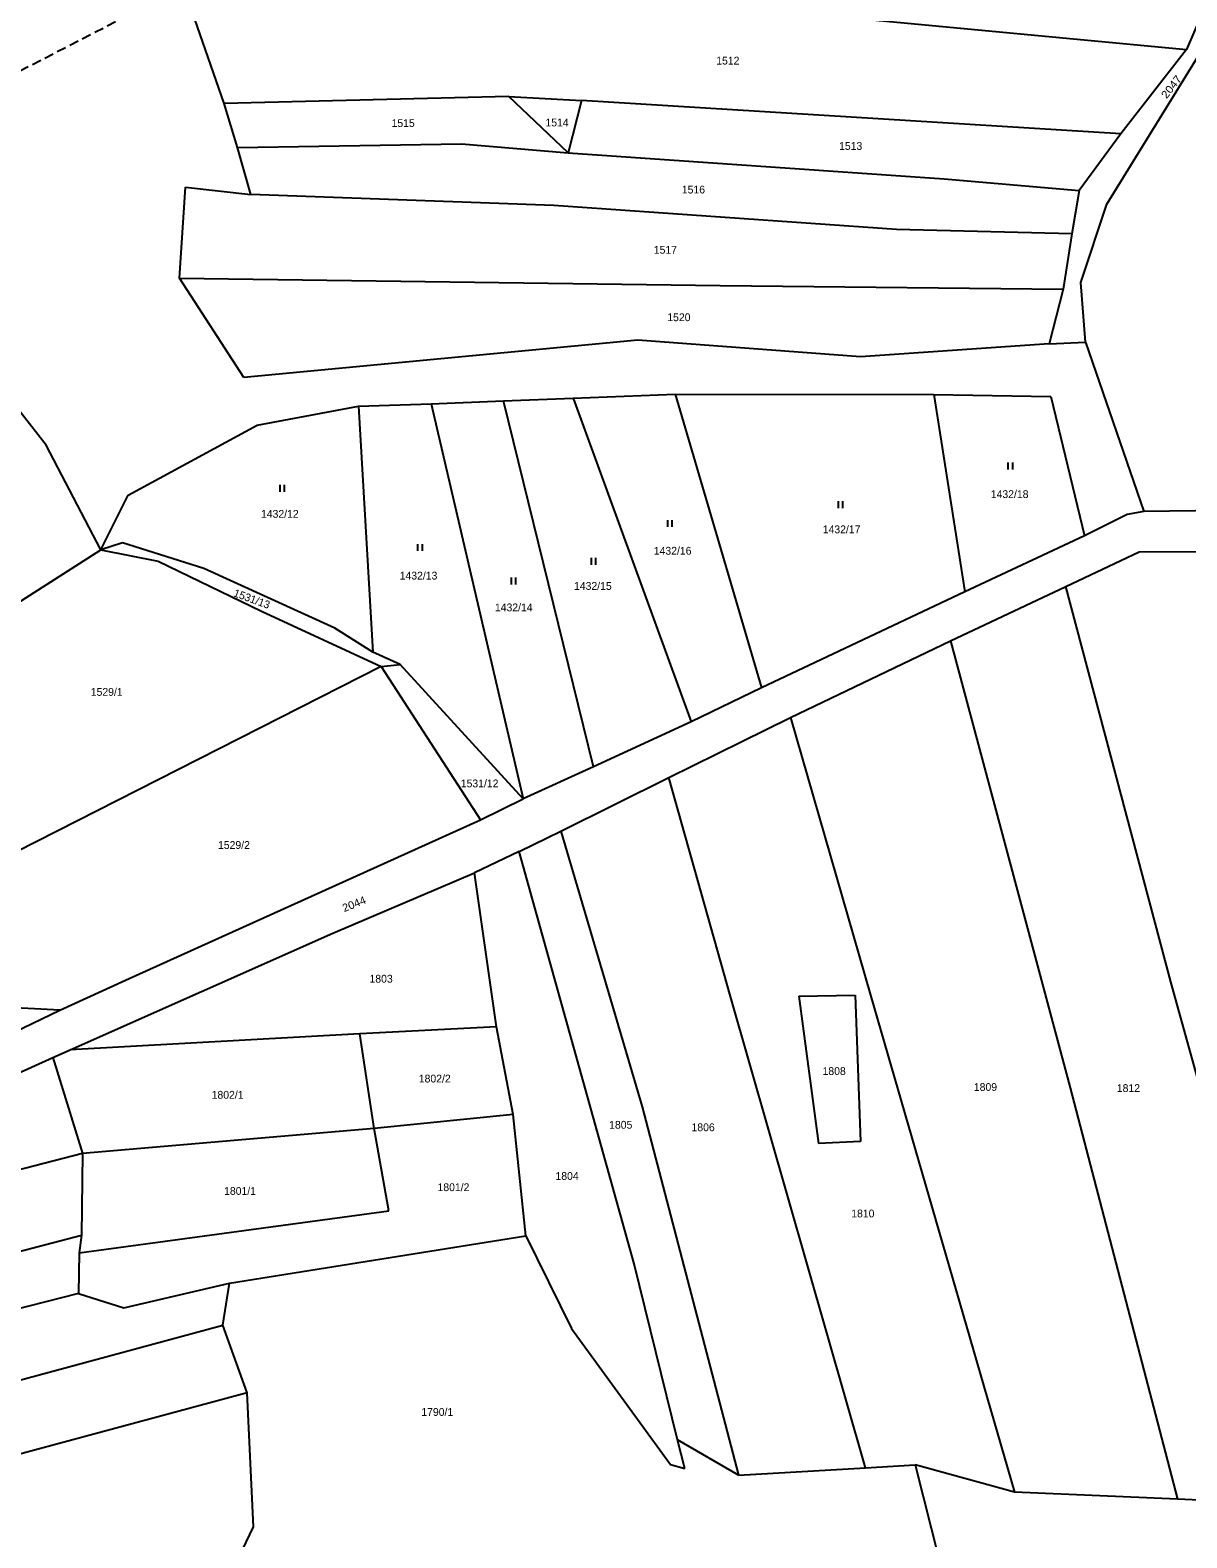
# Model space of a CAD drawing. Extents: x -820420 to -815896, y -1105820 to -1103643.
# Drawn here: x -819110.8 to -818858.6, y -1105141.1 to -1104812.4 of the extents above; entities that cross this region are included whole.
import ezdxf
from ezdxf.enums import TextEntityAlignment as Align

# ---------------------------------------------------------------- set-up
doc = ezdxf.new("R2010")
doc.units = 0
doc.header["$LTSCALE"] = 0.68
doc.linetypes.add('MEDIUM_DASHED', pattern=[4.5, 3, -1.5])
for name, color, linetype, lineweight in [('1', 7, 'Continuous', 25), ('3', 7, 'Continuous', 25), ('6', 7, 'Continuous', 25)]:
    doc.layers.add(name, color=color, linetype=linetype, lineweight=lineweight)
doc.layers.add('2', color=7, linetype='Continuous')

msp = doc.modelspace()

# ---------------------------------------------------------------- linework, layer by layer
at = {"layer": '1'}
for p, q in [((-819068.53, -1104828.41), (-819081.61, -1104790.49)), ((-818852.44, -1104802.17), (-818858.67, -1104816.63)), ((-818985.5, -1104804.65), (-818858.67, -1104816.63)), ((-818876.06, -1104850.4), (-818855.17, -1104816.62)), ((-818858.67, -1104816.63), (-818872.99, -1104835.02)), ((-819006.46, -1104826.94), (-819068.53, -1104828.41)), ((-819065.62, -1104838.05), (-819068.53, -1104828.41)), ((-819006.46, -1104826.94), (-818990.59, -1104827.81)), ((-818993.5, -1104839.21), (-819006.46, -1104826.94)), ((-818990.59, -1104827.81), (-818993.5, -1104839.21)), ((-818872.99, -1104835.02), (-818990.59, -1104827.81)), ((-818872.99, -1104835.02), (-818882.11, -1104847.37)), ((-819065.62, -1104838.05), (-819016.76, -1104837.26)), ((-819062.66, -1104848.28), (-819065.62, -1104838.05)), ((-819016.76, -1104837.26), (-818993.5, -1104839.21)), ((-818993.5, -1104839.21), (-818911.48, -1104844.88)), ((-818911.48, -1104844.88), (-818882.11, -1104847.37)), ((-819078.23, -1104866.53), (-819076.91, -1104846.64)), ((-819076.91, -1104846.64), (-819062.66, -1104848.28)), ((-818996.6, -1104850.68), (-819062.66, -1104848.28)), ((-818882.11, -1104847.37), (-818883.71, -1104856.87)), ((-818921.91, -1104855.87), (-818996.6, -1104850.68)), ((-818881.75, -1104867.43), (-818876.06, -1104850.4)), ((-818883.71, -1104856.87), (-818921.91, -1104855.87)), ((-818883.71, -1104856.87), (-818885.55, -1104868.9)), ((-819078.23, -1104866.53), (-818960.37, -1104868.12)), ((-819064.19, -1104888.18), (-819078.23, -1104866.53)), ((-818960.37, -1104868.12), (-818885.55, -1104868.9)), ((-818885.55, -1104868.9), (-818888.62, -1104880.85)), ((-818880.7, -1104880.5), (-818881.75, -1104867.43)), ((-818978.3, -1104880.01), (-819064.19, -1104888.18)), ((-818929.78, -1104883.69), (-818978.3, -1104880.01)), ((-818888.62, -1104880.85), (-818929.78, -1104883.69)), ((-818888.62, -1104880.85), (-818880.7, -1104880.5)), ((-818880.7, -1104880.5), (-818867.95, -1104917.39)), ((-819107.3, -1104902.93), (-819118.8, -1104888.25)), ((-818992.39, -1104892.68), (-818970.15, -1104891.82)), ((-818970.15, -1104891.82), (-818951.37, -1104955.85)), ((-818970.15, -1104891.82), (-818913.75, -1104891.89)), ((-818913.75, -1104891.89), (-818888.27, -1104892.33)), ((-818913.75, -1104891.89), (-818907.04, -1104934.91)), ((-818888.27, -1104892.33), (-818880.93, -1104922.67)), ((-819061.32, -1104898.56), (-819039.21, -1104894.44)), ((-819039.21, -1104894.44), (-819023.33, -1104893.89)), ((-819039.21, -1104894.44), (-819036.11, -1104948.04)), ((-819023.33, -1104893.89), (-819007.56, -1104893.27)), ((-819023.33, -1104893.89), (-819003.34, -1104980.04)), ((-819007.56, -1104893.27), (-818992.39, -1104892.68)), ((-818987.94, -1104973.07), (-819007.56, -1104893.27)), ((-818992.39, -1104892.68), (-818966.65, -1104963.21)), ((-819089.43, -1104913.83), (-819061.32, -1104898.56)), ((-819095.36, -1104925.76), (-819107.3, -1104902.93)), ((-819095.36, -1104925.76), (-819089.43, -1104913.83)), ((-818871.62, -1104918.02), (-818880.93, -1104922.67)), ((-818867.95, -1104917.39), (-818871.62, -1104918.02)), ((-818821.74, -1104916.82), (-818867.95, -1104917.39)), ((-819090.63, -1104924.18), (-819095.36, -1104925.76)), ((-819072.92, -1104929.78), (-819090.63, -1104924.18)), ((-818880.93, -1104922.67), (-818907.04, -1104934.91)), ((-819139.61, -1104954.03), (-819095.36, -1104925.76)), ((-819095.36, -1104925.76), (-819082.86, -1104928.22)), ((-819082.86, -1104928.22), (-819060.35, -1104939.08)), ((-818885.01, -1104933.75), (-818868.97, -1104926.19)), ((-818868.97, -1104926.19), (-818855.79, -1104926.11)), ((-819044.4, -1104942.84), (-819072.92, -1104929.78)), ((-818907.04, -1104934.91), (-818951.37, -1104955.85)), ((-818910.14, -1104945.59), (-818885.01, -1104933.75)), ((-818862.1, -1105019.93), (-818885.01, -1104933.75)), ((-819060.35, -1104939.08), (-819034.23, -1104951.21)), ((-819036.11, -1104948.04), (-819044.4, -1104942.84)), ((-819030.13, -1104950.77), (-819036.11, -1104948.04)), ((-818945.01, -1104962.27), (-818910.14, -1104945.59)), ((-818910.14, -1104945.59), (-818884.06, -1105043.03)), ((-819034.23, -1104951.21), (-819125.89, -1104997.69)), ((-819034.23, -1104951.21), (-819030.13, -1104950.77)), ((-819034.23, -1104951.21), (-819012.64, -1104984.62)), ((-819003.34, -1104980.04), (-819030.13, -1104950.77)), ((-818951.37, -1104955.85), (-818966.65, -1104963.21)), ((-818966.65, -1104963.21), (-818987.94, -1104973.07)), ((-818971.55, -1104975.38), (-818945.01, -1104962.27)), ((-818945.01, -1104962.27), (-818927.61, -1105022.82)), ((-818987.94, -1104973.07), (-819003.34, -1104980.04)), ((-818995.12, -1104987.04), (-818971.55, -1104975.38)), ((-818958.12, -1105023.1), (-818971.55, -1104975.38)), ((-819012.64, -1104984.62), (-819003.34, -1104980.04)), ((-819089.98, -1105019.56), (-819012.64, -1104984.62)), ((-819004.15, -1104991.5), (-818995.12, -1104987.04)), ((-818995.12, -1104987.04), (-818977.38, -1105047.17)), ((-819004.15, -1104991.5), (-819013.91, -1104996.14)), ((-818979.07, -1105081.39), (-819004.15, -1104991.5)), ((-819044.81, -1105009.31), (-819013.91, -1104996.14)), ((-819009.09, -1105029.71), (-819013.91, -1104996.14)), ((-819102.09, -1105034.72), (-819044.81, -1105009.31)), ((-819104.33, -1105026.11), (-819089.98, -1105019.56)), ((-818830.53, -1105133.99), (-818862.1, -1105019.93)), ((-818928.66, -1105125.87), (-818958.12, -1105023.1)), ((-818943.19, -1105023.04), (-818930.92, -1105022.8)), ((-818943.19, -1105023.04), (-818938.93, -1105055.15)), ((-818930.92, -1105022.8), (-818929.77, -1105054.73)), ((-818927.61, -1105022.82), (-818896.19, -1105131.22)), ((-819104.33, -1105026.11), (-819119.36, -1105025.34)), ((-819114.29, -1105030.92), (-819104.33, -1105026.11)), ((-819009.09, -1105029.71), (-819038.9, -1105031.24)), ((-819005.49, -1105048.86), (-819009.09, -1105029.71)), ((-819038.9, -1105031.24), (-819102.09, -1105034.72)), ((-819035.77, -1105051.87), (-819038.9, -1105031.24)), ((-819140.59, -1105052.26), (-819105.87, -1105036.39)), ((-819105.87, -1105036.39), (-819102.09, -1105034.72)), ((-819105.87, -1105036.39), (-819099.39, -1105057.35)), ((-818884.06, -1105043.03), (-818860.63, -1105132.72)), ((-819005.49, -1105048.86), (-819035.77, -1105051.87)), ((-819002.74, -1105075.32), (-819005.49, -1105048.86)), ((-818977.38, -1105047.17), (-818956.35, -1105127.45)), ((-819035.77, -1105051.87), (-819099.39, -1105057.35)), ((-819032.61, -1105069.86), (-819035.77, -1105051.87)), ((-818929.77, -1105054.73), (-818938.93, -1105055.15)), ((-819099.39, -1105057.35), (-819129.73, -1105065.19)), ((-819099.39, -1105057.35), (-819099.6, -1105075.15)), ((-819100.12, -1105078.98), (-819032.61, -1105069.86)), ((-819193.16, -1105099.72), (-819099.6, -1105075.15)), ((-819099.6, -1105075.15), (-819100.12, -1105078.98)), ((-819067.33, -1105085.59), (-819002.74, -1105075.32)), ((-819002.74, -1105075.32), (-818992.75, -1105095.51)), ((-819100.12, -1105078.98), (-819100.27, -1105087.9)), ((-818969.64, -1105119.76), (-818979.07, -1105081.39)), ((-819090.34, -1105090.98), (-819067.33, -1105085.59)), ((-819068.82, -1105094.78), (-819067.33, -1105085.59)), ((-819100.27, -1105087.9), (-819165.22, -1105104.41)), ((-819100.27, -1105087.9), (-819090.34, -1105090.98)), ((-819180.44, -1105124.94), (-819068.82, -1105094.78)), ((-819063.49, -1105109.52), (-819068.82, -1105094.78)), ((-818992.75, -1105095.51), (-818971.17, -1105125.18)), ((-819063.49, -1105109.52), (-819177.24, -1105140.22)), ((-819062.08, -1105138.76), (-819063.49, -1105109.52)), ((-818968.07, -1105125.99), (-818969.64, -1105119.76)), ((-818956.35, -1105127.45), (-818969.64, -1105119.76)), ((-818971.17, -1105125.18), (-818968.07, -1105125.99)), ((-818956.35, -1105127.45), (-818928.66, -1105125.87)), ((-818928.66, -1105125.87), (-818917.81, -1105125.25)), ((-818917.81, -1105125.25), (-818912.64, -1105145.95)), ((-818896.19, -1105131.22), (-818917.81, -1105125.25)), ((-818860.63, -1105132.72), (-818896.19, -1105131.22)), ((-818830.53, -1105133.99), (-818860.63, -1105132.72)), ((-819066.16, -1105147.22), (-819062.08, -1105138.76))]:
    msp.add_line(p, q, dxfattribs=at)
at = {"layer": '3'}
for p, q in [((-818897.561, -1104908.22), (-818897.561, -1104906.72)), ((-818896.56, -1104908.22), (-818896.56, -1104906.72)), ((-819056.311, -1104913.09), (-819056.311, -1104911.59)), ((-819055.31, -1104913.09), (-819055.31, -1104911.59)), ((-818934.581, -1104916.64), (-818934.581, -1104915.14)), ((-818933.58, -1104916.64), (-818933.58, -1104915.14)), ((-818971.791, -1104920.76), (-818971.791, -1104919.26)), ((-818970.79, -1104920.76), (-818970.79, -1104919.26)), ((-819026.251, -1104925.99), (-819026.251, -1104924.49)), ((-819025.25, -1104925.99), (-819025.25, -1104924.49)), ((-818988.431, -1104928.99), (-818988.431, -1104927.49)), ((-818987.43, -1104928.99), (-818987.43, -1104927.49)), ((-819005.871, -1104933.29), (-819005.871, -1104931.79)), ((-819004.87, -1104933.29), (-819004.87, -1104931.79))]:
    msp.add_line(p, q, dxfattribs=at)
at = {"layer": '6', "linetype": 'MEDIUM_DASHED'}
msp.add_line((-819070.43, -1104799.41), (-819167, -1104849.28), dxfattribs=at)

# ---------------------------------------------------------------- texts
at = {"layer": '2'}
for s, p in [('1512', (-818958.68, -1104819.935)), ('1515', (-819029.47, -1104833.555)), ('1514', (-818995.92, -1104833.425)), ('1513', (-818931.9, -1104838.535)), ('1516', (-818966.18, -1104848.045)), ('1517', (-818972.29, -1104861.175)), ('1520', (-818969.35, -1104875.885)), ('1432/18', (-818897.239, -1104914.445)), ('1432/12', (-819056.359, -1104918.745)), ('1432/17', (-818933.879, -1104922.125)), ('1432/16', (-818970.719, -1104926.795)), ('1432/13', (-819026.119, -1104932.215)), ('1432/15', (-818988.109, -1104934.465)), ('1432/14', (-819005.359, -1104939.145)), ('1529/1', (-819094.1, -1104957.565)), ('1531/12', (-819012.799, -1104977.515)), ('1529/2', (-819066.36, -1104990.945)), ('1803', (-819034.28, -1105020.095)), ('1802/2', (-819022.58, -1105041.865)), ('1808', (-818935.5, -1105040.235)), ('1802/1', (-819067.75, -1105045.405)), ('1809', (-818902.51, -1105043.705)), ('1812', (-818871.34, -1105043.945)), ('1805', (-818982.03, -1105051.945)), ('1806', (-818964.07, -1105052.485)), ('1804', (-818993.73, -1105063.105)), ('1801/1', (-819065.03, -1105066.365)), ('1801/2', (-819018.5, -1105065.555)), ('1810', (-818929.24, -1105071.275)), ('1790/1', (-819022.03, -1105114.555))]:
    msp.add_text(s, height=1.7, dxfattribs=at).set_placement(p, align=Align.CENTER)
for s, rotation, width, p in [('2047', 52, 1.1, (-818861.3066, -1104825.3248)), ('2044', 22, 1.05, (-819039.8584, -1105003.7381))]:
    msp.add_text(s, height=1.7, rotation=rotation, dxfattribs=dict(at, width=width)).set_placement(p, align=Align.CENTER)
msp.add_text('1531/13', height=1.7, rotation=340, dxfattribs=at).set_placement((-819062.7472, -1104937.2331), align=Align.CENTER)

doc.saveas('drawing.dxf')
